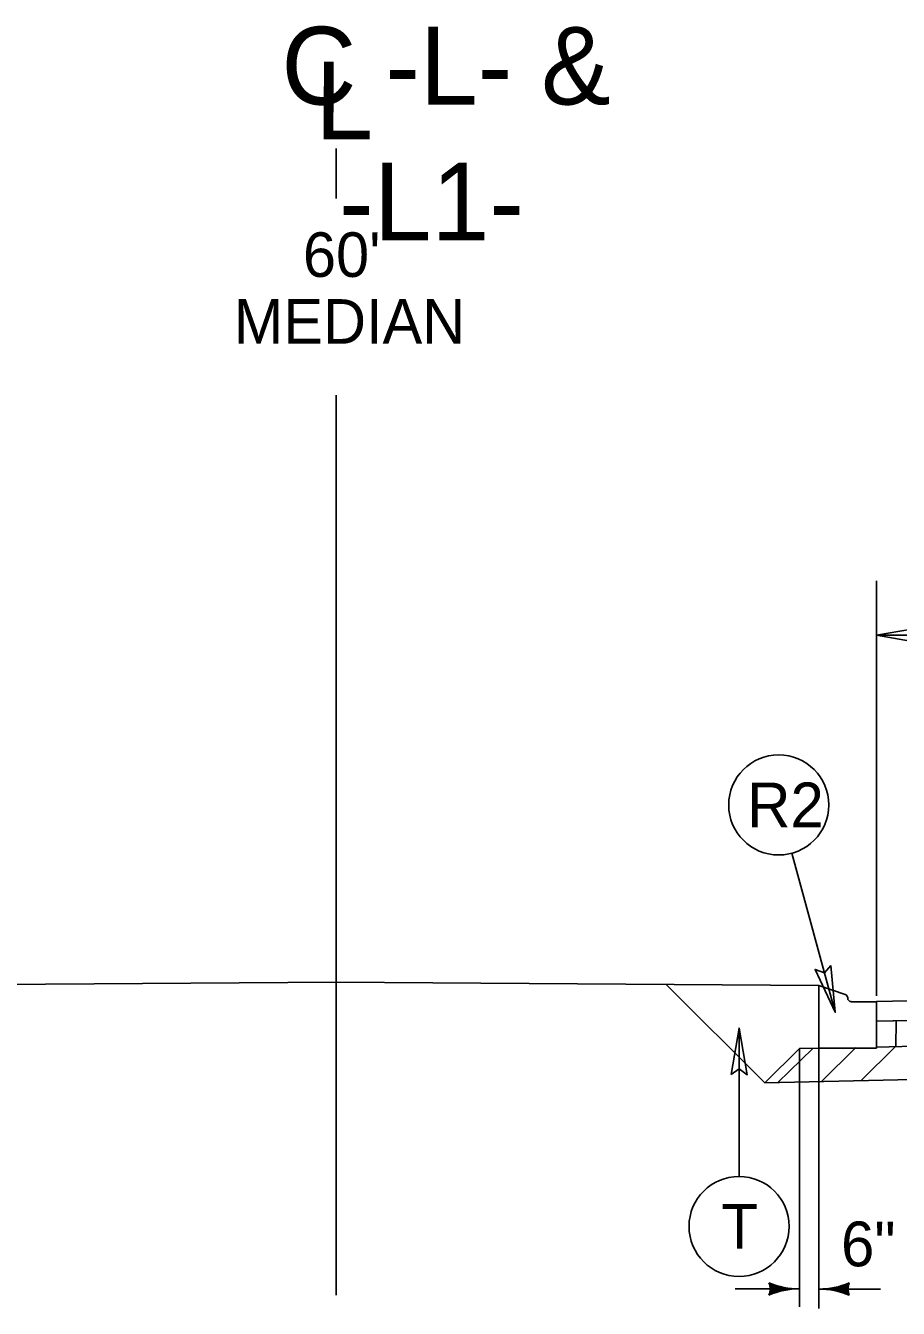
# Model space of a CAD drawing. Extents: x 2176024 to 2177225, y 75947 to 76635.
# Drawn here: x 2176267.8 to 2176290.4, y 76559.47 to 76592.7 of the extents above; entities that cross this region are included whole.
import ezdxf

# ---------------------------------------------------------------- set-up
doc = ezdxf.new("R2010")
doc.units = 0
for name, color, linetype in [('Old_Level_1', 7, 'Continuous'), ('Old_Level_11', 7, 'Continuous'), ('Prop Dimension', 7, 'Continuous'), ('Typical Curb CELL', 7, 'Continuous'), ('Typical Pavement Slope CELL', 7, 'Continuous'), ('Typical Shoulder Slope CELL', 7, 'Continuous'), ('Typical Slope Point Local CELL', 7, 'Continuous'), ('Typical Terminator CELL', 7, 'Continuous'), ('Typical Text General CELL', 7, 'Continuous'), ('Typical Text Label CELL', 7, 'Continuous')]:
    doc.layers.add(name, color=color, linetype=linetype)

msp = doc.modelspace()

# ---------------------------------------------------------------- linework, layer by layer
at = {"layer": 'Old_Level_1'}
for p, q in [((2176288.341, 76566.202), (2176288.341, 76567.827)), ((2176288.341, 76567.827), (2176289.027, 76567.598)), ((2176289.091, 76567.509), (2176289.091, 76567.504)), ((2176289.185, 76567.41), (2176289.841, 76567.41)), ((2176289.841, 76567.41), (2176289.841, 76566.202)), ((2176290.341, 76566.243), (2176290.347, 76566.915)), ((2176287.284, 76565.314), (2176288.185, 76566.2)), ((2176289.841, 76566.202), (2176288.341, 76566.202)), ((2176288.403, 76565.337), (2176289.304, 76566.223)), ((2176289.43, 76565.36), (2176290.329, 76566.245))]:
    msp.add_line(p, q, dxfattribs=at)
for centre, start, end in [((2176288.997, 76567.509), 0, 71.5651), ((2176289.185, 76567.504), 180, 270)]:
    msp.add_arc(centre, 0.0937, start, end, dxfattribs=at)
at = {"layer": 'Old_Level_11'}
for p, q in [((2176287.645, 76571.256), (2176288.768, 76567.138)), ((2176286.277, 76562.883), (2176286.277, 76566.725)), ((2176287.841, 76566.193), (2176287.841, 76559.507)), ((2176288.341, 76566.203), (2176288.341, 76559.465)), ((2176286.174, 76559.969), (2176287.841, 76559.969)), ((2176289.941, 76559.965), (2176288.341, 76559.965))]:
    msp.add_line(p, q, dxfattribs=at)
for points in [[(2176288.656, 76568.35), (2176288.768, 76567.138), (2176288.248, 76568.247), (2176288.494, 76568.155)], [(2176286.07, 76565.525), (2176286.277, 76566.725), (2176286.49, 76565.518), (2176286.277, 76565.672)]]:
    msp.add_lwpolyline(points, close=True, dxfattribs=at)
for centre in [(2176287.305, 76572.507), (2176286.277, 76561.587)]:
    msp.add_circle(centre, 1.296, dxfattribs=at)
for centre, radius, start, end in [((2176286.633, 76559.969), 0.448, 339.2343, 20.766), ((2176287.816, 76561.884), 1.915, 246.4848, 270.7622), ((2176287.816, 76561.884), 1.942, 247.1893, 260.4638), ((2176287.816, 76561.884), 1.969, 247.7696, 256.6115), ((2176287.816, 76561.884), 1.995, 248.2502, 253.7031), ((2176288.367, 76561.88), 1.915, 269.2382, 293.5156), ((2176288.367, 76561.88), 1.942, 279.5367, 292.8111), ((2176288.367, 76561.88), 1.969, 283.389, 292.2308), ((2176288.367, 76561.88), 1.995, 286.2973, 291.7503), ((2176289.55, 76559.965), 0.448, 159.2344, 200.7661), ((2176287.816, 76558.053), 1.915, 89.2381, 113.5155), ((2176287.816, 76558.053), 1.942, 99.5365, 112.811), ((2176287.816, 76558.053), 1.969, 103.3888, 112.2307), ((2176287.816, 76558.053), 1.995, 106.2972, 111.7501), ((2176287.816, 76561.884), 2.022, 248.6472, 251.2913), ((2176287.816, 76558.053), 2.022, 108.709, 111.3531), ((2176288.367, 76558.05), 1.915, 66.4849, 90.7623), ((2176288.367, 76558.05), 1.942, 67.1895, 80.4639), ((2176288.367, 76558.05), 1.969, 67.7698, 76.6116), ((2176288.367, 76558.05), 1.995, 68.2503, 73.7032), ((2176288.367, 76561.88), 2.022, 288.7091, 291.3532), ((2176288.367, 76558.05), 2.022, 68.6473, 71.2914)]:
    msp.add_arc(centre, radius, start, end, dxfattribs=at)
at = {"layer": 'Prop Dimension'}
for p, q in [((2176275.841, 76588.218), (2176275.841, 76589.511)), ((2176275.841, 76559.808), (2176275.841, 76583.126)), ((2176289.841, 76567.563), (2176289.841, 76578.316)), ((2176289.841, 76576.903), (2176293.841, 76576.903))]:
    msp.add_line(p, q, dxfattribs=at)
at = {"layer": 'Typical Curb CELL'}
for p, q in [((2176288.341, 76566.202), (2176288.341, 76567.827)), ((2176289.027, 76567.598), (2176288.341, 76567.827)), ((2176289.091, 76567.504), (2176289.091, 76567.509)), ((2176289.841, 76567.41), (2176289.185, 76567.41)), ((2176289.841, 76566.202), (2176289.841, 76567.41)), ((2176289.841, 76566.202), (2176288.341, 76566.202))]:
    msp.add_line(p, q, dxfattribs=at)
for centre, start, end in [((2176288.997, 76567.509), 0, 71.5651), ((2176289.185, 76567.504), 180, 270)]:
    msp.add_arc(centre, 0.0937, start, end, dxfattribs=at)
at = {"layer": 'Typical Pavement Slope CELL'}
for p, q in [((2176263.341, 76567.833), (2176275.841, 76567.917)), ((2176288.341, 76567.833), (2176275.841, 76567.917)), ((2176284.377, 76567.86), (2176286.947, 76565.304)), ((2176305.345, 76567.227), (2176289.841, 76566.904)), ((2176287.841, 76566.193), (2176286.947, 76565.304)), ((2176288.341, 76566.203), (2176287.841, 76566.193)), ((2176305.841, 76565.736), (2176286.947, 76565.304))]:
    msp.add_line(p, q, dxfattribs=at)
at = {"layer": 'Typical Shoulder Slope CELL'}
msp.add_line((2176305.841, 76566.568), (2176289.841, 76566.235), dxfattribs=at)
at = {"layer": 'Typical Slope Point Local CELL'}
msp.add_lwpolyline([(2176305.12, 76567.735), (2176289.841, 76567.417), (2176289.841, 76566.904), (2176305.345, 76567.227)], dxfattribs=at)
at = {"layer": 'Typical Terminator CELL'}
msp.add_lwpolyline([(2176291.35, 76577.163), (2176289.841, 76576.903), (2176291.359, 76576.634), (2176291.166, 76576.903)], close=True, dxfattribs=at)

# ---------------------------------------------------------------- texts
at = {"layer": 'Old_Level_11'}
for s, rotation, p in [('R2', 0.0003, (2176286.489, 76571.927)), ('T', 359.9997, (2176285.82, 76561.007)), ('6"', 0.0002, (2176288.919, 76560.554))]:
    msp.add_text(s, height=1.16, rotation=rotation, dxfattribs=at).set_placement(p)
at = {"layer": 'Typical Text General CELL'}
for s, p in [("60'", (2176274.979, 76586.187)), ('MEDIAN', (2176273.186, 76584.457))]:
    msp.add_text(s, height=1.1533, dxfattribs=at).set_placement(p)
at = {"layer": 'Typical Text Label CELL'}
for s, p in [('C -L- & ', (2176274.42, 76590.653)), ('  -L1-', (2176274.42, 76587.131))]:
    msp.add_text(s, height=2.0131, dxfattribs=at).set_placement(p)
msp.add_text('L', height=2.013, rotation=359.9469, dxfattribs=at).set_placement((2176275.298, 76589.751))

doc.saveas('drawing.dxf')
